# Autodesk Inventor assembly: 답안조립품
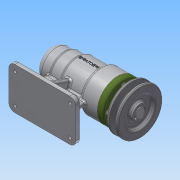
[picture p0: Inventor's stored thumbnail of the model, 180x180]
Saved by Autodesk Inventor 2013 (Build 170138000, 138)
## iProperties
Created: 2016-06
Part Number: 답안조립품
Document SubType Name: Assembly
Designer: mrc
Author: mrc
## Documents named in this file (12)
- C:\Users\mrc\Desktop\460608V1023\답안조립품.iam
- C:\Users\mrc\Desktop\460608V1023\V벨트풀리.ipt
- C:\Users\mrc\Desktop\460608V1023\멈춤나사 M3x8.ipt
- C:\Users\mrc\Desktop\460608V1023\베어링 6004.ipt
- C:\Users\mrc\Desktop\460608V1023\베어링 51202.ipt
- C:\Users\mrc\Desktop\460608V1023\본체.ipt
- C:\Users\mrc\Desktop\460608V1023\볼트 M4 x 12.ipt
- C:\Users\mrc\Desktop\460608V1023\어댑터슬리브.ipt
- C:\Users\mrc\Desktop\460608V1023\오일 실.ipt
- C:\Users\mrc\Desktop\460608V1023\축.ipt
- C:\Users\mrc\Desktop\460608V1023\커버.ipt
- C:\Users\mrc\Desktop\460608V1023\키 5 x 5 x 16.ipt
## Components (5 placed, 2 different names)
1. V벨트풀리:1 — 플러쉬:1
2. ISO 4762 M4 x 12:1
3. ISO 4762 M4 x 12:2
4. ISO 4762 M4 x 12:3
5. ISO 4762 M4 x 12:4
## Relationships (1: Flush 1)
- 플러쉬:1 [Flush]: V벨트풀리:1
